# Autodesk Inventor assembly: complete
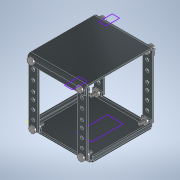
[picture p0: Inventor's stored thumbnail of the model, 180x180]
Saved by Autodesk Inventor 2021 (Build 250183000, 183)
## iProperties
Created: 2021-07
Part Number: complete
Document SubType Name: Assembly
Designer: user
Author: user
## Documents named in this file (4)
- C:\Users\user\Downloads\complete.iam
- C:\Users\user\Downloads\lower part new.ipt
- C:\Users\user\Downloads\bolt new.ipt
- C:\Users\user\Downloads\nut new.ipt
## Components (17 placed, 3 different names)
1. lower part new:1 — Rotational:1, Rigid:1, Rotational:2, Rotational:3, Rotational:4, Rotational:5, Rotational:6, Rotational:7, Rotational:8, Rotational:9
2. bolt new:1 — Rotational:2, Rigid:2
3. bolt new:2 — Rotational:5
4. bolt new:3 — Rotational:1, Rigid:4
5. bolt new:4 — Rotational:3, Rigid:3
6. bolt new:5 — Rotational:4
7. bolt new:6 — Rotational:7, Rigid:8
8. bolt new:7 — Rotational:6, Rigid:9
9. bolt new:8 — Rigid:1, Rigid:7
10. nut new:1 — Rigid:2
11. nut new:2 — Rigid:3
12. nut new:3 — Rigid:4
13. nut new:5 — Rigid:9
14. nut new:6 — Rigid:8
15. nut new:7 — Rigid:7
16. nut new:9 — Rotational:8
17. nut new:10 — Rotational:9
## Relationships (16: RevoluteJoint 9, WeldJoint 7)
- Rotational:1 [RevoluteJoint]: lower part new:1 ↔ bolt new:3
- Rigid:1 [WeldJoint]: lower part new:1 ↔ bolt new:8
- Rotational:2 [RevoluteJoint]: lower part new:1 ↔ bolt new:1
- Rotational:3 [RevoluteJoint]: lower part new:1 ↔ bolt new:4
- Rotational:4 [RevoluteJoint]: lower part new:1 ↔ bolt new:5
- Rotational:5 [RevoluteJoint]: lower part new:1 ↔ bolt new:2
- Rotational:6 [RevoluteJoint]: lower part new:1 ↔ bolt new:7
- Rotational:7 [RevoluteJoint]: lower part new:1 ↔ bolt new:6
- Rigid:2 [WeldJoint]: bolt new:1 ↔ nut new:1
- Rigid:3 [WeldJoint]: bolt new:4 ↔ nut new:2
- Rigid:4 [WeldJoint]: bolt new:3 ↔ nut new:3
- Rigid:7 [WeldJoint]: bolt new:8 ↔ nut new:7
- Rigid:8 [WeldJoint]: bolt new:6 ↔ nut new:6
- Rigid:9 [WeldJoint]: bolt new:7 ↔ nut new:5
- Rotational:8 [RevoluteJoint]: lower part new:1 ↔ nut new:9
- Rotational:9 [RevoluteJoint]: lower part new:1 ↔ nut new:10
